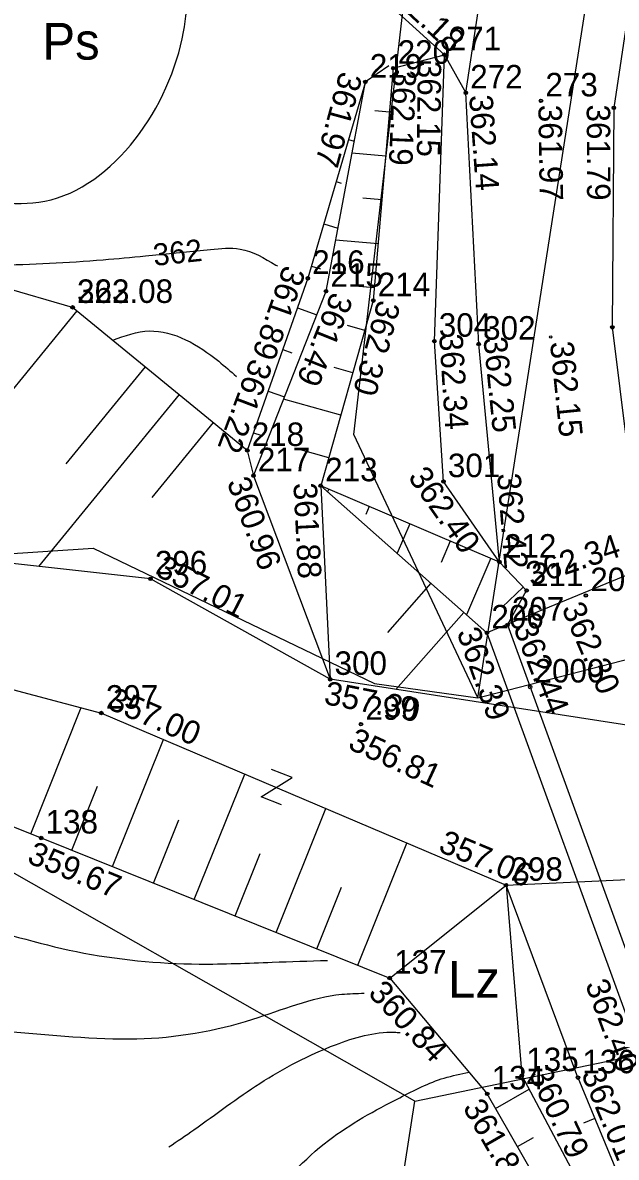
# Model space of a CAD drawing. Extents: x 4635329 to 4651863, y 5356628 to 5367582.
# Drawn here: x 4651713.58 to 4651733.8, y 5357115.3 to 5357153.92 of the extents above; entities that cross this region are included whole.
import ezdxf

# ---------------------------------------------------------------- set-up
doc = ezdxf.new("R2010")
doc.units = 0
for name, color, linetype in [('Level 12', 7, 'Continuous'), ('Level 20', 7, 'Continuous'), ('Level 29', 7, 'Continuous'), ('Level 4', 7, 'Continuous'), ('Level 44', 7, 'Continuous'), ('Level 45', 7, 'Continuous'), ('Level 46', 7, 'Continuous'), ('Level 47', 7, 'Continuous'), ('Level 48', 7, 'Continuous'), ('Level 50', 7, 'Continuous'), ('Level 53', 7, 'Continuous'), ('Level 63', 7, 'Continuous')]:
    doc.layers.add(name, color=color, linetype=linetype)

msp = doc.modelspace()

# ---------------------------------------------------------------- linework, layer by layer
at = {"layer": 'Level 20'}
for points in [[(4651729.82, 5357135.56), (4651729.11, 5357142.98), (4651728.67, 5357151.53), (4651729.317, 5357155.805), (4651729.9, 5357158.7), (4651733.24, 5357168.87), (4651737.34, 5357179.25), (4651742.57, 5357192.12), (4651752.49, 5357216.86)], [(4651756.54, 5357214.25), (4651747.08, 5357190.33), (4651742.11, 5357177.45), (4651737.72, 5357166.81), (4651734.98, 5357158.12), (4651734.207, 5357154.352), (4651733.71, 5357151.02), (4651733.66, 5357143.55), (4651734.7, 5357135.16)], [(4651703.46, 5357166.53), (4651721.83, 5357156.87), (4651725.65, 5357154.91), (4651727.94, 5357152.83), (4651728.67, 5357151.53)], [(4651730.09, 5357133.42), (4651735.37, 5357118.93)]]:
    msp.add_lwpolyline(points, dxfattribs=at)
at = {"layer": 'Level 29'}
msp.add_lwpolyline([(4651734.66, 5357118.67), (4651740.74, 5357121.04), (4651735.37, 5357135.61), (4651729.39, 5357133.15)], close=True, dxfattribs=at)
at = {"layer": 'Level 4'}
for p, q in [((4651729.077, 5357130.935), (4651733.96, 5357162.18)), ((4651724.857, 5357139.906), (4651726.979, 5357158.218)), ((4651729.077, 5357130.935), (4651724.857, 5357139.906)), ((4651676.592, 5357133.424), (4651715.978, 5357136.035)), ((4651715.978, 5357136.035), (4651725.559, 5357131.425)), ((4651729.077, 5357130.935), (4651738.202, 5357133.305)), ((4651725.559, 5357131.425), (4651729.077, 5357130.935)), ((4651726.932, 5357117.207), (4651711.734, 5357125.845)), ((4651726.932, 5357117.207), (4651734.382, 5357118.748)), ((4651726.34, 5357113.42), (4651726.932, 5357117.207))]:
    msp.add_line(p, q, dxfattribs=at)
at = {"layer": 'Level 44'}
for centre in [(4651727.94, 5357152.83), (4651726.2, 5357152.37), (4651725.25, 5357151.9), (4651728.67, 5357151.53), (4651731.23, 5357151.26), (4651733.71, 5357151.02), (4651723.29, 5357145.22), (4651723.91, 5357144.78), (4651715.28, 5357144.23), (4651725.52, 5357144.46), (4651733.66, 5357143.55), (4651727.6, 5357143.08), (4651731.562, 5357143.223), (4651729.11, 5357142.98), (4651721.23, 5357139.36), (4651721.44, 5357138.5), (4651723.73, 5357138.16), (4651727.91, 5357138.3), (4651729.82, 5357135.56), (4651717.93, 5357134.99), (4651730.74, 5357134.59), (4651732.76, 5357134.42), (4651730.09, 5357133.42), (4651729.39, 5357133.15), (4651724.05, 5357131.57), (4651716.26, 5357130.42), (4651725.1, 5357130.04), (4651714.21, 5357126.17), (4651730.04, 5357124.56), (4651726.08, 5357121.4), (4651730.58, 5357118.08), (4651732.49, 5357118.01), (4651729.4, 5357117.46)]:
    msp.add_circle(centre, 0.04, dxfattribs=at)
at = {"layer": 'Level 46'}
msp.add_line((4651717.767, 5357145.978), (4651719.978, 5357146.194), dxfattribs=at)
for points in [[(4651699.387, 5357150.073), (4651701.719, 5357150.572), (4651704.872, 5357149.784), (4651707.903, 5357148.45), (4651710.995, 5357148.025), (4651714.33, 5357147.843), (4651719.06, 5357153.605), (4651719.242, 5357156.395), (4651719.388, 5357158.154)], [(4651719.978, 5357146.194), (4651720.984, 5357146.215), (4651722.196, 5357145.669), (4651722.262, 5357145.629)], [(4651710.298, 5357145.669), (4651712.677, 5357145.669), (4651716.315, 5357145.851), (4651717.767, 5357145.978)], [(4651716.644, 5357143.113), (4651717.891, 5357143.425), (4651720.255, 5357142.394), (4651720.856, 5357141.877)], [(4651704.704, 5357122.825), (4651708.072, 5357123.819), (4651711.468, 5357123.334), (4651715.409, 5357122.303), (4651719.593, 5357121.878), (4651722.079, 5357121.939), (4651723.958, 5357122)], [(4651679.579, 5357122.474), (4651681.03, 5357121.575), (4651685.335, 5357118.967), (4651690.004, 5357116.965), (4651694.248, 5357115.813), (4651697.947, 5357115.995), (4651702.07, 5357116.905), (4651710.68, 5357119.573), (4651713.105, 5357119.573), (4651717.471, 5357119.331), (4651721.412, 5357119.998), (4651724.443, 5357120.847), (4651725.213, 5357120.884)], [(4651718.56, 5357115.654), (4651719.411, 5357116.238), (4651721.654, 5357117.815), (4651724.232, 5357119.132), (4651726.233, 5357119.556), (4651726.43, 5357119.546)], [(4651715.922, 5357108.895), (4651718.598, 5357110.718), (4651721.751, 5357113.69), (4651723.994, 5357115.873), (4651726.419, 5357117.329), (4651727.935, 5357117.996), (4651728.782, 5357118.194)]]:
    msp.add_spline(points, degree=3, dxfattribs=at)
at = {"layer": 'Level 48'}
for p, q in [((4651725.1, 5357151.387), (4651725.125, 5357151.38)), ((4651726.072, 5357150.876), (4651725.572, 5357150.918)), ((4651724.677, 5357149.948), (4651724.872, 5357149.891)), ((4651725.943, 5357149.381), (4651724.794, 5357149.48)), ((4651724.255, 5357148.509), (4651724.424, 5357148.459)), ((4651725.815, 5357147.887), (4651725.165, 5357147.942)), ((4651723.833, 5357147.07), (4651724.314, 5357146.928)), ((4651725.686, 5357146.392), (4651724.237, 5357146.517)), ((4651723.41, 5357145.63), (4651723.723, 5357145.538)), ((4651725.558, 5357144.898), (4651724.758, 5357144.966)), ((4651715.426, 5357144.11), (4651712.684, 5357140.76)), ((4651722.934, 5357144.208), (4651723.594, 5357143.976)), ((4651725.23, 5357143.44), (4651724.638, 5357143.608)), ((4651722.437, 5357142.793), (4651722.741, 5357142.686)), ((4651717.748, 5357142.21), (4651715.044, 5357138.907)), ((4651724.82, 5357141.997), (4651724.182, 5357142.178)), ((4651718.908, 5357141.26), (4651714.119, 5357135.409)), ((4651721.939, 5357141.378), (4651722.495, 5357141.183)), ((4651724.41, 5357140.554), (4651722.465, 5357141.106)), ((4651720.069, 5357140.31), (4651717.983, 5357137.762)), ((4651721.442, 5357139.963), (4651721.694, 5357139.874)), ((4651724, 5357139.111), (4651722.957, 5357139.407)), ((4651724.003, 5357138.043), (4651723.965, 5357137.953)), ((4651725.383, 5357137.454), (4651725.265, 5357137.18)), ((4651726.762, 5357136.865), (4651726.332, 5357135.857)), ((4651728.142, 5357136.276), (4651727.829, 5357135.543)), ((4651729.521, 5357135.687), (4651728.699, 5357133.761)), ((4651727.483, 5357134.838), (4651726.003, 5357133.167)), ((4651730.629, 5357134.707), (4651729.905, 5357134.021)), ((4651728.606, 5357133.844), (4651726.286, 5357131.224)), ((4651713.857, 5357126.31), (4651715.566, 5357130.604)), ((4651716.641, 5357125.193), (4651718.38, 5357129.519)), ((4651719.425, 5357124.074), (4651721.141, 5357128.344)), ((4651715.25, 5357125.752), (4651716.124, 5357127.929)), ((4651722.209, 5357122.956), (4651723.902, 5357127.17)), ((4651718.033, 5357124.634), (4651718.897, 5357126.783)), ((4651724.992, 5357121.837), (4651726.663, 5357125.996)), ((4651720.817, 5357123.515), (4651721.669, 5357125.636)), ((4651723.6, 5357122.396), (4651724.442, 5357124.49)), ((4651729.684, 5357116.964), (4651730.825, 5357117.619)), ((4651733.063, 5357116.624), (4651732.681, 5357116.466)), ((4651730.431, 5357115.663), (4651730.98, 5357115.978))]:
    msp.add_line(p, q, dxfattribs=at)
for points in [[(4651721.23, 5357139.36), (4651715.28, 5357144.23), (4651708.01, 5357146.33), (4651692.69, 5357152.98), (4651680.43, 5357155.59)], [(4651726.2, 5357152.37), (4651727.94, 5357152.83)], [(4651727.6, 5357143.08), (4651727.94, 5357152.83)], [(4651726.044, 5357152.45), (4651725.25, 5357151.9), (4651723.29, 5357145.22), (4651721.23, 5357139.36)], [(4651726.2, 5357152.37), (4651725.52, 5357144.46), (4651723.73, 5357138.16), (4651729.39, 5357133.15)], [(4651721.44, 5357138.5), (4651723.91, 5357144.78), (4651725.25, 5357151.9)], [(4651729.82, 5357135.56), (4651727.91, 5357138.3), (4651727.6, 5357143.08)], [(4651721.23, 5357139.36), (4651721.44, 5357138.5), (4651724.05, 5357131.57)], [(4651723.73, 5357138.16), (4651724.05, 5357131.57)], [(4651730.09, 5357133.42), (4651730.74, 5357134.59), (4651729.82, 5357135.56), (4651723.73, 5357138.16)], [(4651678.56, 5357132.47), (4651690.82, 5357130.51), (4651708.03, 5357128.63), (4651714.21, 5357126.17), (4651726.08, 5357121.4), (4651729.4, 5357117.46)], [(4651726.08, 5357121.4), (4651730.04, 5357124.56)], [(4651730.04, 5357124.56), (4651730.58, 5357118.08)], [(4651732.49, 5357118.01), (4651730.04, 5357124.56)], [(4651730.58, 5357118.08), (4651733.63, 5357112.336)], [(4651732.49, 5357118.01), (4651734.62, 5357112.86)], [(4651732.67, 5357111.76), (4651729.4, 5357117.46)]]:
    msp.add_lwpolyline(points, dxfattribs=at)
at = {"layer": 'Level 50'}
for p, q in [((4651717.93, 5357134.99), (4651709.92, 5357135.87)), ((4651724.05, 5357131.57), (4651717.93, 5357134.99)), ((4651709.21, 5357132.29), (4651716.26, 5357130.42)), ((4651738.58, 5357129.32), (4651724.05, 5357131.57)), ((4651716.26, 5357130.42), (4651730.04, 5357124.56)), ((4651730.04, 5357124.56), (4651741.05, 5357125.07))]:
    msp.add_line(p, q, dxfattribs=at)
at = {"layer": 'Level 53'}
for p, q in [((4651722.756, 5357128.226), (4651722.056, 5357128.497)), ((4651721.696, 5357127.564), (4651722.756, 5357128.226)), ((4651722.395, 5357127.293), (4651721.696, 5357127.564))]:
    msp.add_line(p, q, dxfattribs=at)
at = {"layer": 'Level 63'}
for centre in [(4651727.94, 5357152.83), (4651726.2, 5357152.37), (4651725.25, 5357151.9), (4651728.67, 5357151.53), (4651731.23, 5357151.26), (4651733.71, 5357151.02), (4651723.29, 5357145.22), (4651723.91, 5357144.78), (4651715.28, 5357144.23), (4651725.52, 5357144.46), (4651733.66, 5357143.55), (4651727.6, 5357143.08), (4651729.11, 5357142.98), (4651721.23, 5357139.36), (4651721.44, 5357138.5), (4651723.73, 5357138.16), (4651727.91, 5357138.3), (4651729.82, 5357135.56), (4651717.93, 5357134.99), (4651730.74, 5357134.59), (4651732.76, 5357134.42), (4651730.09, 5357133.42), (4651729.39, 5357133.15), (4651724.05, 5357131.57), (4651730.86, 5357131.31), (4651730.86, 5357131.31), (4651730.86, 5357131.31), (4651730.86, 5357131.31), (4651716.26, 5357130.42), (4651725.1, 5357130.04), (4651714.21, 5357126.17), (4651730.04, 5357124.56), (4651726.08, 5357121.4), (4651730.58, 5357118.08), (4651732.49, 5357118.01), (4651729.4, 5357117.46)]:
    msp.add_circle(centre, 0.06, dxfattribs=at)

# ---------------------------------------------------------------- texts
at = {"layer": 'Level 12'}
for s, p in [('Ps', (4651714.251, 5357152.661)), ('Lz', (4651728.066, 5357120.732))]:
    msp.add_text(s, height=1.25, dxfattribs=at).set_placement(p)
at = {"layer": 'Level 45'}
for s, rotation, p in [('362.18', 316.9859, (4651725.766, 5357155.074)), ('362.15', 269.4066, (4651727.035, 5357152.626)), ('361.97', 254.7593, (4651724.386, 5357152.294)), ('362.19', 267.6067, (4651726.186, 5357152.339)), ('362.14', 274.0999, (4651728.783, 5357151.44)), ('361.97', 270.8137, (4651731.141, 5357151.121)), ('361.79', 270.2168, (4651732.787, 5357151.134)), ('361.89', 250.4583, (4651722.477, 5357145.702)), ('361.49', 248.2685, (4651724.107, 5357144.791)), ('362.30', 254.8169, (4651725.681, 5357144.517)), ('362.34', 273.6512, (4651727.762, 5357143.307)), ('362.25', 275.7938, (4651729.266, 5357143.189)), ('362.15', 275.7938, (4651731.536, 5357143.037)), ('361.22', 249.3515, (4651721.359, 5357142.529)), ('360.96', 290.4877, (4651720.523, 5357138.278)), ('362.40', 305.0455, (4651726.679, 5357138.451)), ('362.42', 274.525, (4651729.735, 5357138.559)), ('361.88', 272.8903, (4651722.798, 5357138.243)), ('362.34', 18.5727, (4651730.894, 5357134.73)), ('357.01', 332.6572, (4651718.054, 5357135.127)), ('362.30', 293.5316, (4651731.921, 5357133.983)), ('362.44', 291.3528, (4651730.28, 5357133.33)), ('362.39', 289.7612, (4651728.351, 5357133.171)), ('357.00', 336.5061, (4651716.415, 5357130.593)), ('357.30', 348.9368, (4651723.807, 5357130.734)), ('356.81', 335.1756, (4651724.616, 5357129.225)), ('357.06', 337.3682, (4651727.697, 5357125.728)), ('359.67', 337.5787, (4651713.692, 5357125.342)), ('360.84', 313.0284, (4651725.312, 5357120.858)), ('362.40', 290.1915, (4651732.728, 5357121.191)), ('360.79', 295.1052, (4651730.797, 5357118.144)), ('362.01', 292.5802, (4651732.591, 5357118.141)), ('361.81', 299.8433, (4651728.55, 5357116.995))]:
    msp.add_text(s, height=0.8, rotation=rotation, dxfattribs=at).set_placement(p)
msp.add_text('362.08', height=0.8, dxfattribs=at).set_placement((4651715.43, 5357144.38))
at = {"layer": 'Level 47'}
msp.add_text('362', height=0.75, rotation=5.9966, dxfattribs=at).set_placement((4651718.06, 5357145.638))
at = {"layer": 'Level 63'}
for s, p in [('271', (4651728.09, 5357152.98)), ('220', (4651726.35, 5357152.52)), ('219', (4651725.4, 5357152.05)), ('272', (4651728.82, 5357151.68)), ('273', (4651731.38, 5357151.41)), ('216', (4651723.44, 5357145.37)), ('215', (4651724.06, 5357144.93)), ('214', (4651725.67, 5357144.61)), ('223', (4651715.43, 5357144.38)), ('304', (4651727.75, 5357143.23)), ('302', (4651729.26, 5357143.13)), ('218', (4651721.38, 5357139.51)), ('217', (4651721.59, 5357138.65)), ('301', (4651728.06, 5357138.45)), ('213', (4651723.88, 5357138.31)), ('212', (4651729.97, 5357135.71)), ('296', (4651718.08, 5357135.14)), ('211', (4651730.89, 5357134.74)), ('208', (4651732.91, 5357134.57)), ('207', (4651730.24, 5357133.57)), ('206', (4651729.54, 5357133.3)), ('300', (4651724.2, 5357131.72)), ('2000', (4651731.01, 5357131.46)), ('2000', (4651731.01, 5357131.46)), ('2000', (4651731.01, 5357131.46)), ('2000', (4651731.01, 5357131.46)), ('297', (4651716.41, 5357130.57)), ('299', (4651725.25, 5357130.19)), ('138', (4651714.36, 5357126.32)), ('298', (4651730.19, 5357124.71)), ('137', (4651726.23, 5357121.55)), ('135', (4651730.73, 5357118.23)), ('136', (4651732.64, 5357118.16)), ('134', (4651729.55, 5357117.61))]:
    msp.add_text(s, height=0.8, dxfattribs=at).set_placement(p)

doc.saveas('drawing.dxf')
